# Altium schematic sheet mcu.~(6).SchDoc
size A3
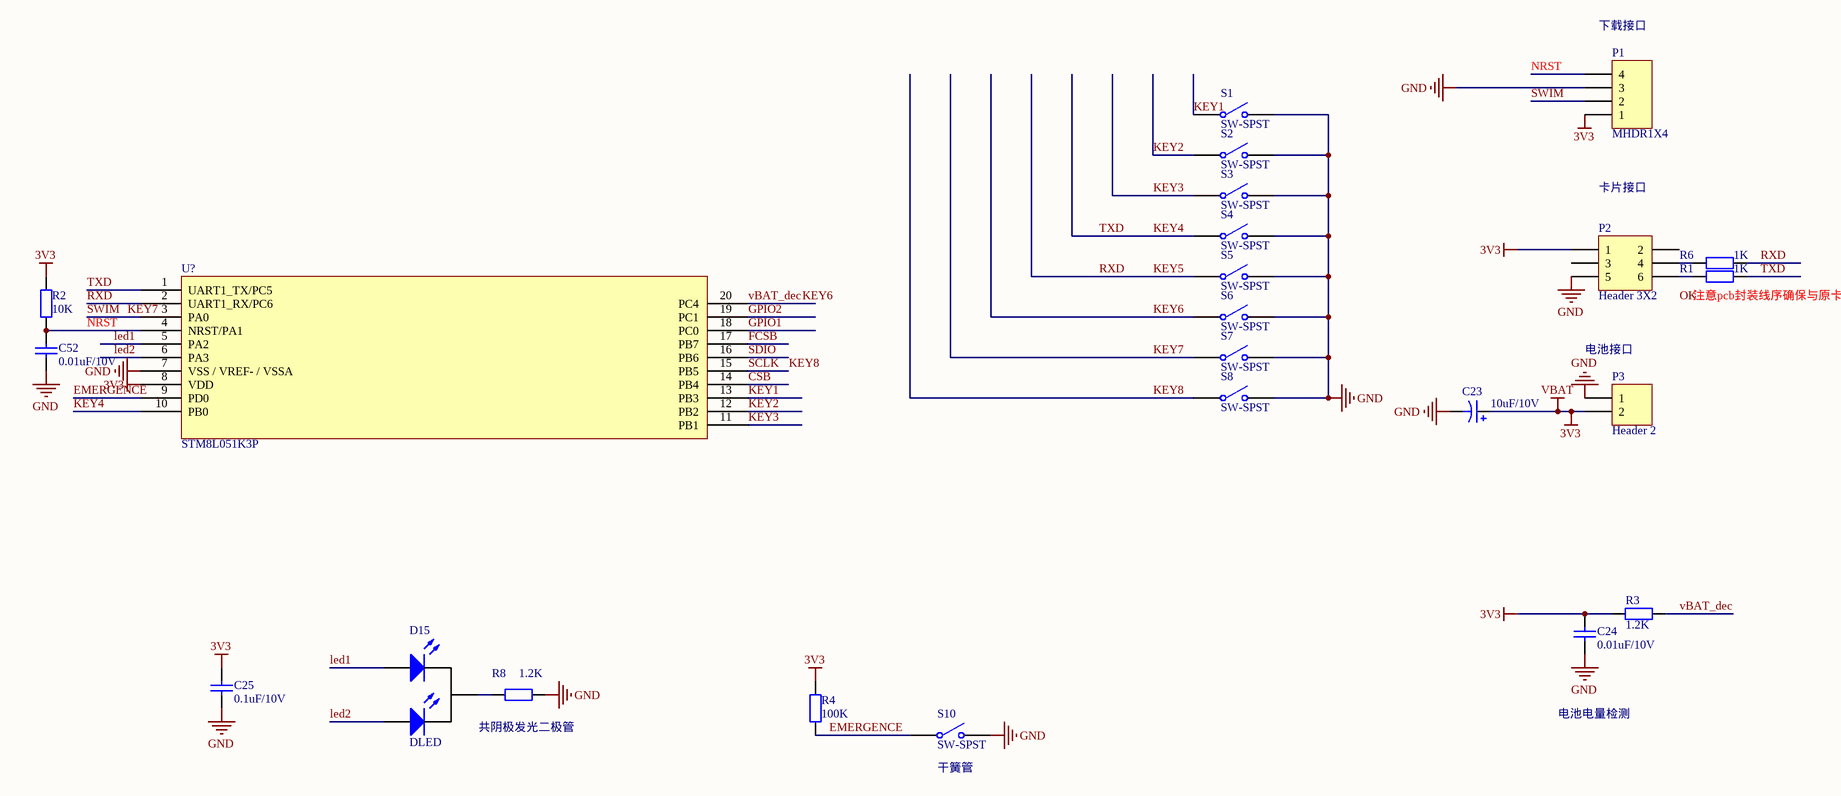
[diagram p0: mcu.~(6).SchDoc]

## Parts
C23  10uF/10V
C24  0.01uF/10V  [0603C]
C25  0.1uF/10V  [0603C]
C52  0.01uF/10V  [0603C]
D15  DLED
P1  MHDR1X4  [SIP4]
P2  Header 3X2
P3  Header 2
R1  1K  [0603R]
R2  10K  [0603R]
R3  1.2K  [0603R]
R4  100K  [0603R]
R6  1K  [0603R]
R8  1.2K  [0603R]
S1  SW-SPST
S2  SW-SPST
S3  SW-SPST
S4  SW-SPST
S5  SW-SPST
S6  SW-SPST
S7  SW-SPST
S8  SW-SPST
S10  SW-SPST
U?  STM8L051K3P

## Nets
3V3: C23.1 C24.1 C25.1 P1.1 P2.1 P3.2 R2.2 R3.2 R4.1 U?.8(VDD)  [also labelled VBAT]
GND: C23.2 C24.2 C25.2 C52.2 P1.3 P2.5 P3.1 R8.1 S1.2(NO) S2.2(NO) S3.2(NO) S4.2(NO) S5.2(NO) S6.2(NO) S7.2(NO) S8.2(NO) S10.2(NO) U?.7(VSS_/_VREF-_/_VSSA)
CSB: U?.14(PB4)
EMERGENCE: R4.2 S10.1(COMMON) U?.9(PD0)
FCSB: U?.17(PB7)
GPIO1: U?.18(PC0)
GPIO2: U?.19(PC1)
KEY1: S1.1(COMMON) U?.13(PB3)
KEY2: S2.1(COMMON) U?.12(PB2)
KEY3: S3.1(COMMON) U?.11(PB1)
KEY4: R1.1 S4.1(COMMON) U?.1(UART1_TX/PC5) U?.10(PB0)  [also labelled TXD]
KEY5: R6.1 S5.1(COMMON) U?.2(UART1_RX/PC6)  [also labelled RXD]
KEY6: R3.1 S6.1(COMMON) U?.20(PC4)  [also labelled vBAT_dec]
KEY7: P1.2 S7.1(COMMON) U?.3(PA0)  [also labelled SWIM]
KEY8: S8.1(COMMON) U?.15(PB5)  [also labelled SCLK]
led1: D15.1(A) U?.5(PA2)
led2: D15.3(A) U?.6(PA3)
NRST: C52.1 P1.4 R2.1 U?.4(NRST/PA1)
SDIO: U?.16(PB6)
NetD15_2: D15.2(K) R8.2
NetP2_4: P2.4 R6.2
NetP2_6: P2.6 R1.2

Not connected (* = marked no-connect by the designer): P2 2 3

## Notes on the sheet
- (near P1) 下载接口
- 卡片接口
- (near R1) 注意pcb封装线序确保与原卡片接口一致
- (near P3) 电池接口
- 共阴极发光二极管
- 电池电量检测
- (near S10) 干簧管
- Labels drawn without touching a wire or pin: OK

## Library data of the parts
C23 = Cap Pol1: Polarized Capacitor (Radial); Value: 100pF
C24 C25 C52 = Cap: Capacitor; Value: 106
P1 = MHDR1X4: Header, 4-Pin
P2 = Header 3X2: Header, 3-Pin, Dual row
P3 = Header 2: Header, 2-Pin
R1-R4 R6 R8 = Res2: Resistor; Value: 10K/5%/1/8W
S1-S8 S10 = SW-SPST: Single-Pole, Single-Throw Switch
